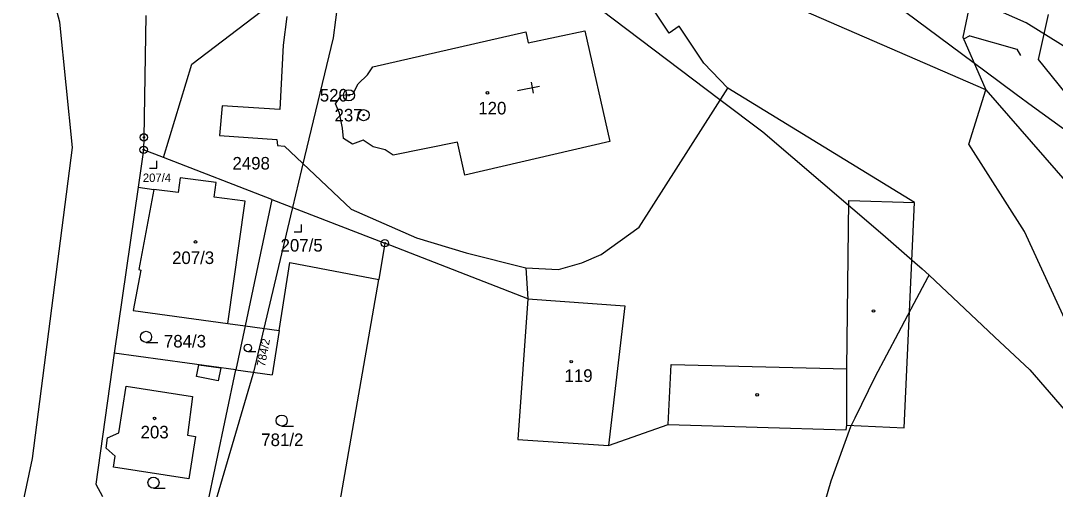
# Model space of a CAD drawing. Extents: x -546762 to -540209, y -1046851 to -1035694.
# Drawn here: x -542604.8 to -542465, y -1039792.3 to -1039728.9 of the extents above; entities that cross this region are included whole.
import ezdxf

# ---------------------------------------------------------------- set-up
doc = ezdxf.new("R2010")
doc.units = 0
for name, color, linetype in [('Vrstva 1', 7, 'Continuous'), ('Vrstva 17', 7, 'Continuous'), ('Vrstva 18', 7, 'Continuous'), ('Vrstva 19', 7, 'Continuous'), ('Vrstva 24', 7, 'Continuous'), ('Vrstva 25', 7, 'Continuous'), ('Vrstva 26', 7, 'Continuous'), ('Vrstva 3', 7, 'Continuous'), ('Vrstva 30', 7, 'Continuous'), ('Vrstva 37', 7, 'Continuous'), ('Vrstva 4', 7, 'Continuous'), ('Vrstva 52', 7, 'Continuous'), ('Vrstva 6', 7, 'Continuous')]:
    doc.layers.add(name, color=color, linetype=linetype)

msp = doc.modelspace()

# ---------------------------------------------------------------- linework, layer by layer
at = {"layer": 'Vrstva 1'}
msp.add_line((-542568.44, -1039761.63), (-542556.45, -1039763.93), dxfattribs=at)
for points in [[(-542474.43, -1039738.26), (-542529.4, -1039714.33)], [(-542599.52, -1039729.12), (-542603.22, -1039715.27)], [(-542517.21, -1039730.58), (-542526.29, -1039716.9)], [(-542581.68, -1039734.78), (-542567.18, -1039723.72)], [(-542476.1, -1039724.21), (-542477.53, -1039731.15)], [(-542597.83, -1039746.04), (-542599.52, -1039729.12)], [(-542587.91, -1039728.19), (-542588.18, -1039744.69)], [(-542568.87, -1039728.32), (-542569.34, -1039732.21)], [(-542467.34, -1039734.17), (-542465.97, -1039728.06)], [(-542515.88, -1039729.65), (-542517.21, -1039730.58)], [(-542512.55, -1039734.65), (-542515.88, -1039729.65)], [(-542477.53, -1039731.15), (-542474.43, -1039738.26)], [(-542569.34, -1039732.21), (-542569.81, -1039740.92)], [(-542509.31, -1039738.04), (-542512.55, -1039734.65)], [(-542458.24, -1039745.42), (-542467.34, -1039734.17)], [(-542585.52, -1039747.41), (-542581.68, -1039734.78)], [(-542521.28, -1039756.82), (-542509.31, -1039738.04)], [(-542484.07, -1039753.51), (-542509.31, -1039738.04)], [(-542476.74, -1039745.62), (-542474.43, -1039738.26)], [(-542474.43, -1039738.26), (-542460.34, -1039754.45)], [(-542577.62, -1039740.43), (-542577.97, -1039744.45)], [(-542569.81, -1039740.92), (-542577.62, -1039740.43)], [(-542577.97, -1039744.45), (-542570.21, -1039744.99)], [(-542588.18, -1039744.69), (-542588.21, -1039746.37)], [(-542570.21, -1039744.99), (-542570.12, -1039745.79)], [(-542570.12, -1039745.79), (-542569.16, -1039745.89)], [(-542569.16, -1039745.89), (-542560.18, -1039754.41)], [(-542469.21, -1039757.41), (-542476.74, -1039745.62)], [(-542603.21, -1039788.14), (-542597.83, -1039746.04)], [(-542588.21, -1039746.37), (-542588.94, -1039751.44)], [(-542585.52, -1039747.41), (-542588.21, -1039746.37)], [(-542570.91, -1039753.07), (-542585.52, -1039747.41)], [(-542588.94, -1039751.44), (-542592.17, -1039773.87)], [(-542588.94, -1039751.44), (-542586.84, -1039751.72)], [(-542583.28, -1039750.17), (-542583.54, -1039752.15)], [(-542578.41, -1039750.81), (-542583.28, -1039750.17)], [(-542578.67, -1039752.79), (-542578.41, -1039750.81)], [(-542586.84, -1039751.72), (-542588.85, -1039762.58)], [(-542583.54, -1039752.15), (-542586.84, -1039751.72)], [(-542574.48, -1039753.34), (-542578.67, -1039752.79)], [(-542576.83, -1039769.85), (-542574.48, -1039753.34)], [(-542570.91, -1039753.07), (-542574.51, -1039770.17)], [(-542570.91, -1039753.07), (-542555.62, -1039759.01)], [(-542485.45, -1039783.99), (-542484.07, -1039753.51)], [(-542560.18, -1039754.41), (-542551.35, -1039758.26)], [(-542526.39, -1039760.53), (-542521.28, -1039756.82)], [(-542551.35, -1039758.26), (-542544.66, -1039760.31)], [(-542445.02, -1039810.02), (-542469.21, -1039757.41)], [(-542555.62, -1039759.01), (-542556.45, -1039763.93)], [(-542536.32, -1039766.53), (-542555.62, -1039759.01)], [(-542544.66, -1039760.31), (-542536.6, -1039762.34)], [(-542529.01, -1039761.65), (-542526.39, -1039760.53)], [(-542588.61, -1039762.63), (-542589.62, -1039768.09)], [(-542588.85, -1039762.58), (-542588.61, -1039762.63)], [(-542569.89, -1039770.8), (-542568.44, -1039761.63)], [(-542536.6, -1039762.34), (-542536.32, -1039766.53)], [(-542536.6, -1039762.34), (-542532.16, -1039762.54)], [(-542532.16, -1039762.54), (-542529.01, -1039761.65)], [(-542563.71, -1039805.78), (-542556.45, -1039763.93)], [(-542536.32, -1039766.53), (-542537.67, -1039785.57)], [(-542589.62, -1039768.09), (-542576.83, -1039769.85)], [(-542576.83, -1039769.85), (-542574.51, -1039770.17)], [(-542574.51, -1039770.17), (-542569.89, -1039770.8)], [(-542569.89, -1039770.8), (-542570.84, -1039776.81)], [(-542592.17, -1039773.87), (-542594.65, -1039791.59)], [(-542575.76, -1039776.13), (-542592.17, -1039773.87)], [(-542581, -1039801.03), (-542575.76, -1039776.13)], [(-542575.76, -1039776.13), (-542570.84, -1039776.81)], [(-542591.56, -1039784.65), (-542590.59, -1039778.33)], [(-542590.59, -1039778.33), (-542581.61, -1039779.75)], [(-542581.61, -1039779.75), (-542582.3, -1039784.96)], [(-542525.42, -1039786.37), (-542517.35, -1039783.52)], [(-542517.35, -1039783.52), (-542493.31, -1039784.24)], [(-542493.31, -1039784.24), (-542493.23, -1039783.61)], [(-542493.23, -1039783.61), (-542485.45, -1039783.99)], [(-542593.08, -1039785.33), (-542591.56, -1039784.65)], [(-542582.3, -1039784.96), (-542581.21, -1039785.13)], [(-542593.29, -1039786.71), (-542593.08, -1039785.33)], [(-542581.21, -1039785.13), (-542582.09, -1039790.86)], [(-542537.67, -1039785.57), (-542525.42, -1039786.37)], [(-542592.04, -1039787.82), (-542593.29, -1039786.71)], [(-542592.3, -1039789.3), (-542592.04, -1039787.82)], [(-542608.77, -1039813.99), (-542603.21, -1039788.14)], [(-542582.09, -1039790.86), (-542592.3, -1039789.3)], [(-542594.65, -1039791.59), (-542593.79, -1039793.26)]]:
    msp.add_lwpolyline(points, dxfattribs=at)
at = {"layer": 'Vrstva 24'}
for centre, radius in [((-542560.48, -1039738.99), 0.75), ((-542560.48, -1039738.99), 0.1), ((-542558.49, -1039741.68), 0.75), ((-542558.49, -1039741.68), 0.1), ((-542588.18, -1039744.69), 0.5), ((-542588.21, -1039746.37), 0.5), ((-542588.18, -1039744.69), 0.1), ((-542588.21, -1039746.37), 0.1), ((-542555.62, -1039759.01), 0.5), ((-542555.62, -1039759.01), 0.1)]:
    msp.add_circle(centre, radius, dxfattribs=at)
at = {"layer": 'Vrstva 25'}
for p, q in [((-542535.87, -1039737.23), (-542535.58, -1039738.71)), ((-542537.69, -1039738.35), (-542534.74, -1039737.78)), ((-542587.88, -1039772.42), (-542586.28, -1039772.42)), ((-542574.14, -1039773.67), (-542573.07, -1039773.67)), ((-542569.55, -1039783.74), (-542567.95, -1039783.74)), ((-542586.88, -1039792.14), (-542585.28, -1039792.14))]:
    msp.add_line(p, q, dxfattribs=at)
for points in [[(-542587.44, -1039748.85), (-542586.44, -1039748.85), (-542586.44, -1039747.85)], [(-542567.89, -1039757.46), (-542566.89, -1039757.46), (-542566.89, -1039756.46)]]:
    msp.add_lwpolyline(points, dxfattribs=at)
for centre, radius in [((-542541.77, -1039738.67), 0.175), ((-542581.2, -1039758.83), 0.175), ((-542489.6, -1039768.17), 0.175), ((-542587.88, -1039771.67), 0.75), ((-542574.14, -1039773.17), 0.503), ((-542530.44, -1039775.03), 0.175), ((-542505.32, -1039779.51), 0.175), ((-542569.55, -1039782.99), 0.75), ((-542586.73, -1039782.7), 0.175), ((-542586.88, -1039791.39), 0.75)]:
    msp.add_circle(centre, radius, dxfattribs=at)
at = {"layer": 'Vrstva 26'}
for p, q in [((-542476.58, -1039730.94), (-542477.45, -1039731.42)), ((-542470.23, -1039732.76), (-542469.74, -1039733.63))]:
    msp.add_line(p, q, dxfattribs=at)
at = {"layer": 'Vrstva 3'}
for points in [[(-542557.24, -1039735.16), (-542536.56, -1039730.41)], [(-542536.56, -1039730.41), (-542536.24, -1039731.92)], [(-542536.24, -1039731.92), (-542528.61, -1039730.27)], [(-542528.61, -1039730.27), (-542525.25, -1039745.27)], [(-542557.95, -1039736.25), (-542557.24, -1039735.16)], [(-542559.97, -1039738.85), (-542559.21, -1039737.46)], [(-542559.21, -1039737.46), (-542557.95, -1039736.25)], [(-542561.5, -1039738.99), (-542559.97, -1039738.85)], [(-542562.3, -1039740.17), (-542561.5, -1039738.99)], [(-542561.73, -1039741.43), (-542562.3, -1039740.17)], [(-542561.33, -1039743.46), (-542561.73, -1039741.43)], [(-542561.23, -1039744.86), (-542561.33, -1039743.46)], [(-542560, -1039745.61), (-542561.23, -1039744.86)], [(-542558.56, -1039745.06), (-542560, -1039745.61)], [(-542557.21, -1039745.95), (-542558.56, -1039745.06)], [(-542545.79, -1039745.35), (-542554.48, -1039747.09)], [(-542544.82, -1039749.78), (-542545.79, -1039745.35)], [(-542525.25, -1039745.27), (-542544.82, -1039749.78)], [(-542555.57, -1039746.37), (-542557.21, -1039745.95)], [(-542554.48, -1039747.09), (-542555.57, -1039746.37)], [(-542583.28, -1039750.17), (-542583.54, -1039752.15)], [(-542578.41, -1039750.81), (-542583.28, -1039750.17)], [(-542578.67, -1039752.79), (-542578.41, -1039750.81)], [(-542586.84, -1039751.72), (-542588.85, -1039762.58)], [(-542583.54, -1039752.15), (-542586.84, -1039751.72)], [(-542574.48, -1039753.34), (-542578.67, -1039752.79)], [(-542576.83, -1039769.85), (-542574.48, -1039753.34)], [(-542588.61, -1039762.63), (-542589.62, -1039768.09)], [(-542588.85, -1039762.58), (-542588.61, -1039762.63)], [(-542536.32, -1039766.53), (-542537.67, -1039785.57)], [(-542536.32, -1039766.53), (-542523.22, -1039767.47)], [(-542589.62, -1039768.09), (-542576.83, -1039769.85)], [(-542523.22, -1039767.47), (-542525.42, -1039786.37)], [(-542591.56, -1039784.65), (-542590.59, -1039778.33)], [(-542590.59, -1039778.33), (-542581.61, -1039779.75)], [(-542581.61, -1039779.75), (-542582.3, -1039784.96)], [(-542593.08, -1039785.33), (-542591.56, -1039784.65)], [(-542582.3, -1039784.96), (-542581.21, -1039785.13)], [(-542593.29, -1039786.71), (-542593.08, -1039785.33)], [(-542581.21, -1039785.13), (-542582.09, -1039790.86)], [(-542537.67, -1039785.57), (-542525.42, -1039786.37)], [(-542592.04, -1039787.82), (-542593.29, -1039786.71)], [(-542592.3, -1039789.3), (-542592.04, -1039787.82)], [(-542582.09, -1039790.86), (-542592.3, -1039789.3)]]:
    msp.add_lwpolyline(points, dxfattribs=at)
at = {"layer": 'Vrstva 30'}
msp.add_lwpolyline([(-542578.12, -1039777.6), (-542581.07, -1039777.05), (-542580.77, -1039775.44), (-542577.79, -1039775.85), (-542578.12, -1039777.6)], dxfattribs=at)
at = {"layer": 'Vrstva 37'}
for centre in [(-542541.77, -1039738.67), (-542581.2, -1039758.83), (-542530.44, -1039775.03), (-542586.73, -1039782.7)]:
    msp.add_circle(centre, 0.175, dxfattribs=at)
at = {"layer": 'Vrstva 4'}
for points in [[(-542557.24, -1039735.16), (-542536.56, -1039730.41)], [(-542536.56, -1039730.41), (-542536.24, -1039731.92)], [(-542536.24, -1039731.92), (-542528.61, -1039730.27)], [(-542528.61, -1039730.27), (-542525.25, -1039745.27)], [(-542476.58, -1039730.94), (-542470.23, -1039732.76)], [(-542557.95, -1039736.25), (-542557.24, -1039735.16)], [(-542559.97, -1039738.85), (-542559.21, -1039737.46)], [(-542559.21, -1039737.46), (-542557.95, -1039736.25)], [(-542561.5, -1039738.99), (-542559.97, -1039738.85)], [(-542562.3, -1039740.17), (-542561.5, -1039738.99)], [(-542561.73, -1039741.43), (-542562.3, -1039740.17)], [(-542561.33, -1039743.46), (-542561.73, -1039741.43)], [(-542561.23, -1039744.86), (-542561.33, -1039743.46)], [(-542560, -1039745.61), (-542561.23, -1039744.86)], [(-542558.56, -1039745.06), (-542560, -1039745.61)], [(-542557.21, -1039745.95), (-542558.56, -1039745.06)], [(-542545.79, -1039745.35), (-542554.48, -1039747.09)], [(-542544.82, -1039749.78), (-542545.79, -1039745.35)], [(-542525.25, -1039745.27), (-542544.82, -1039749.78)], [(-542555.57, -1039746.37), (-542557.21, -1039745.95)], [(-542554.48, -1039747.09), (-542555.57, -1039746.37)], [(-542493.22, -1039775.98), (-542492.94, -1039753.24)], [(-542492.94, -1039753.24), (-542484.07, -1039753.51)], [(-542536.32, -1039766.53), (-542523.22, -1039767.47)], [(-542523.22, -1039767.47), (-542525.42, -1039786.37)], [(-542517.35, -1039783.52), (-542516.94, -1039775.41)], [(-542516.94, -1039775.41), (-542493.22, -1039775.98)], [(-542493.23, -1039783.61), (-542493.22, -1039775.98)]]:
    msp.add_lwpolyline(points, dxfattribs=at)
at = {"layer": 'Vrstva 52'}
for points in [[(-542425.69, -1039756.13), (-542468.98, -1039729.2), (-542474.7, -1039726.68), (-542499.07, -1039670.62), (-542511.07, -1039620.92)], [(-542264.49, -1039875.43), (-542290.85, -1039858.55), (-542318.14, -1039841.08), (-542343.79, -1039824.66), (-542388.93, -1039795.76), (-542396.76, -1039790.75), (-542415.13, -1039778.98), (-542420.87, -1039774.81), (-542457.7, -1039748.07), (-542468.13, -1039740.5), (-542470.35, -1039738.88), (-542474.58, -1039735.72), (-542489.95, -1039724.24), (-542502.54, -1039714.4), (-542511.91, -1039707.08), (-542517.44, -1039702.76), (-542528.12, -1039694.42), (-542529.68, -1039693.2), (-542534.76, -1039689.23), (-542553.67, -1039674.45), (-542563.85, -1039666.49)], [(-542560, -1039701.93), (-542560.42, -1039712.27), (-542560.43, -1039712.56), (-542560.52, -1039714.74), (-542561.68, -1039723.86), (-542562.61, -1039731.22), (-542566.46, -1039747.32), (-542568.09, -1039754.16), (-542568.36, -1039755.28), (-542571.96, -1039770.52), (-542573.37, -1039776.46), (-542573.44, -1039776.75), (-542580.64, -1039801.14)], [(-542560, -1039701.93), (-542554.13, -1039706.38), (-542544.39, -1039713.76), (-542510.38, -1039739.55), (-542504.58, -1039743.95), (-542488.37, -1039757.82), (-542484.04, -1039761.61), (-542483.05, -1039762.48), (-542482.1, -1039763.31)], [(-542452.16, -1039955.34), (-542465.49, -1039930.76), (-542467.46, -1039926.72), (-542480.26, -1039900.42), (-542488.38, -1039881.87), (-542490.27, -1039877.55), (-542491.11, -1039875.04), (-542495.2, -1039862.76), (-542497.74, -1039851.1), (-542498.78, -1039841.5), (-542499.34, -1039832.92), (-542499.48, -1039830.7), (-542499.83, -1039825.36), (-542499.53, -1039816.84), (-542499.08, -1039807.27), (-542497.44, -1039798.46), (-542495.35, -1039791.13), (-542492.66, -1039783.81), (-542492.07, -1039782.61), (-542489.37, -1039777.09), (-542486.23, -1039771.11), (-542484.12, -1039767.13), (-542482.27, -1039763.63), (-542482.1, -1039763.31)], [(-542482.1, -1039763.31), (-542473.26, -1039771.65), (-542468.51, -1039776.12), (-542455.18, -1039791.55), (-542449.83, -1039799.25), (-542446.81, -1039803.58), (-542439.04, -1039814.92), (-542436.81, -1039818.17), (-542428.71, -1039829.93), (-542421.91, -1039840.13)]]:
    msp.add_lwpolyline(points, dxfattribs=at)
at = {"layer": 'Vrstva 6'}
msp.add_lwpolyline([(-542574.51, -1039770.17), (-542575.76, -1039776.13)], dxfattribs=at)

# ---------------------------------------------------------------- texts
at = {"layer": 'Vrstva 17'}
for s, p in [('520', (-542564.41, -1039739.84)), ('237', (-542562.42, -1039742.53))]:
    msp.add_text(s, height=1.7, dxfattribs=at).set_placement(p)
at = {"layer": 'Vrstva 18'}
for s, p in [('2498', (-542576.21, -1039749.04)), ('784/3', (-542585.47, -1039773.11)), ('781/2', (-542572.32, -1039786.44))]:
    msp.add_text(s, height=1.7, dxfattribs=at).set_placement(p)
msp.add_text('784/2', height=1.14, rotation=79.4309, dxfattribs=at).set_placement((-542571.83, -1039775.77))
at = {"layer": 'Vrstva 19'}
for s, height, p in [('120', 1.7, (-542543, -1039741.59)), ('207/4', 1.14, (-542588.32, -1039750.72)), ('207/5', 1.7, (-542569.71, -1039760.14)), ('207/3', 1.7, (-542584.37, -1039761.82)), ('119', 1.7, (-542531.35, -1039777.76)), ('203', 1.7, (-542588.62, -1039785.4))]:
    msp.add_text(s, height=height, dxfattribs=at).set_placement(p)

doc.saveas('drawing.dxf')
